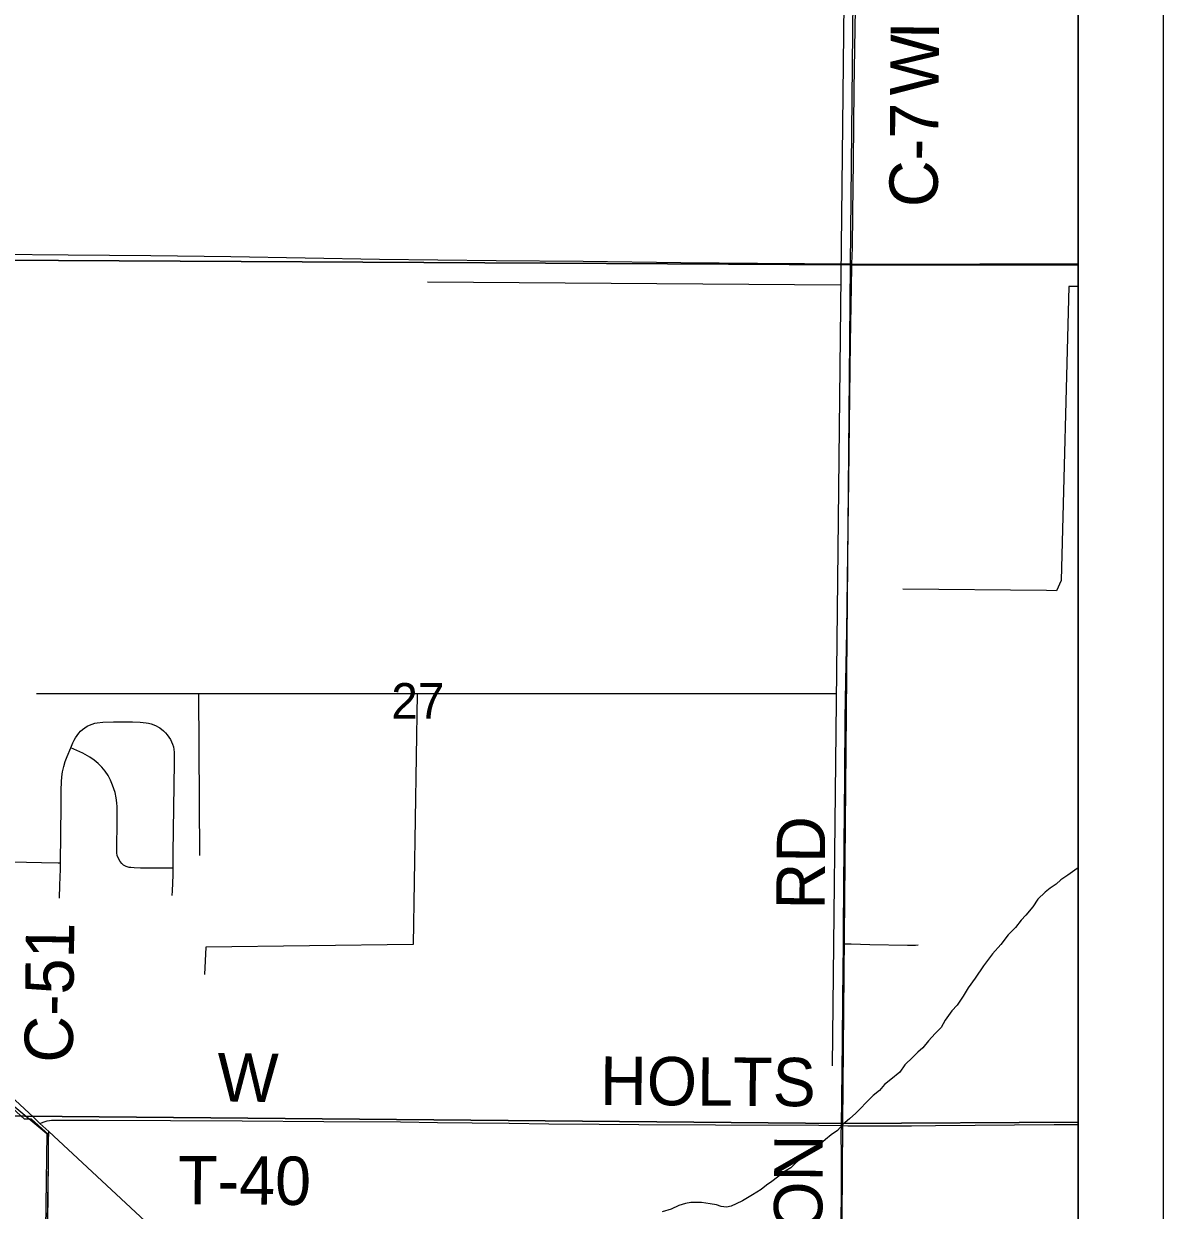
# Model space of a CAD drawing. Extents: x 0 to 34, y 0 to 22.
# Drawn here: x 7.662 to 9, y 15.265 to 16.658 of the extents above; entities that cross this region are included whole.
import ezdxf

# ---------------------------------------------------------------- set-up
doc = ezdxf.new("R2010")
doc.units = 0
for name, color, linetype in [('Default', 7, 'Continuous'), ('GM_X_City_Street', 7, 'Continuous'), ('GM_X_County_Road', 7, 'Continuous'), ('GM_X_County_Road_Text', 7, 'Continuous'), ('GM_X_Interstate_Route', 7, 'Continuous'), ('GM_X_Minor_River', 7, 'Continuous'), ('GM_X_Rail_Line', 7, 'Continuous'), ('GM_X_Section', 7, 'Continuous'), ('GM_X_Section_Text', 7, 'Continuous'), ('GM_X_State_Route', 7, 'Continuous'), ('GM_X_Township_Road', 7, 'Continuous'), ('GM_X_Township_Road_Text', 7, 'Continuous'), ('SH_Data', 7, 'Continuous')]:
    doc.layers.add(name, color=color, linetype=linetype)

msp = doc.modelspace()

# ---------------------------------------------------------------- linework, layer by layer
at = {"layer": 'Default'}
for points in [[(8.9, 16.3752), (8.9, 17.3884), (8.6426, 17.3907), (8.6324, 16.375)], [(8.9, 15.3679), (8.9, 16.3752), (8.6324, 16.375), (8.6234, 15.3665)], [(8.9, 14.3602), (8.9, 15.3679), (8.6234, 15.3665), (8.6163, 14.3591)]]:
    msp.add_lwpolyline(points, close=True, dxfattribs=at)
msp.add_lwpolyline([(7.6895, 15.2493), (7.6905, 15.323), (7.6906, 15.3451), (7.6906, 15.3534), (7.6708, 15.3714), (7.6625, 15.3715), (7.5256, 15.497)], dxfattribs=at)
at = {"layer": 'GM_X_City_Street'}
msp.add_lwpolyline([(7.6898, 15.2488), (7.6908, 15.3224), (7.6908, 15.3446), (7.6912, 15.3569)], dxfattribs=at)
at = {"layer": 'GM_X_County_Road'}
msp.add_lwpolyline([(8.6342, 16.3763), (8.6349, 16.395), (8.6355, 16.4353), (8.6362, 16.4974), (8.6371, 16.5811), (8.6381, 16.6525), (8.6401, 16.7673), (8.6405, 16.8107), (8.641, 16.851), (8.641, 16.879), (8.6415, 16.9251), (8.6423, 16.9966), (8.6427, 17.0214), (8.6428, 17.0275), (8.6432, 17.0337), (8.6436, 17.0377), (8.6447, 17.0437), (8.6458, 17.0492), (8.6475, 17.055), (8.6495, 17.0616), (8.666, 17.1117), (8.684, 17.1672), (8.6935, 17.1966), (8.696, 17.2047)], dxfattribs=at)
at = {"layer": 'GM_X_Interstate_Route'}
msp.add_lwpolyline([(8.9, 14.1), (8.9, 17.3895), (8.6473, 17.3907), (8.6467, 17.3907), (8.6346, 17.3907), (8.4804, 17.3959), (8.4711, 17.3964), (8.44, 17.397), (8.3187, 17.398), (8.2657, 17.3984), (8.1319, 17.3996), (8.079, 17.4004), (7.9794, 17.4011), (7.9078, 17.4018), (7.8424, 17.4022), (7.7241, 17.4025), (7.6681, 17.4026), (7.6399, 17.4028)], dxfattribs=at)
at = {"layer": 'GM_X_Minor_River'}
for points in [[(8.6229, 17.264), (8.6309, 17.2534), (8.611, 15.4343)], [(8.621, 16.351), (8.136, 16.3547)], [(8.9, 16.3497), (8.8891, 16.3497), (8.8799, 16.0041), (8.8746, 15.992), (8.8629, 15.9924), (8.6942, 15.994)], [(8.6158, 15.871), (7.6767, 15.8712)], [(7.867, 15.8712), (7.8681, 15.6813)], [(8.1237, 15.8711), (8.119, 15.5767), (7.8756, 15.5734), (7.8737, 15.5415)], [(8.9, 15.6665), (8.8988, 15.6658), (8.8881, 15.6582), (8.8798, 15.6525), (8.8741, 15.6476), (8.8673, 15.643), (8.8612, 15.6381), (8.8525, 15.6301), (8.8468, 15.621), (8.8385, 15.6111), (8.8332, 15.6051), (8.8263, 15.5967), (8.818, 15.588), (8.8093, 15.5766), (8.7994, 15.5656), (8.7888, 15.5516), (8.7789, 15.5371), (8.771, 15.5257), (8.7649, 15.5159), (8.7581, 15.5053), (8.7516, 15.4988), (8.744, 15.4878), (8.7391, 15.4791), (8.7319, 15.4722), (8.7243, 15.4635), (8.7175, 15.4552), (8.7118, 15.4502), (8.7057, 15.4442), (8.6966, 15.4354), (8.6906, 15.4267), (8.68, 15.4183), (8.6727, 15.4123), (8.6667, 15.4051), (8.6591, 15.3994), (8.6508, 15.3906), (8.6447, 15.3846), (8.639, 15.3785), (8.6314, 15.3721), (8.6235, 15.3652), (8.6174, 15.3584), (8.6098, 15.3531), (8.6034, 15.3478), (8.5973, 15.3425), (8.5889, 15.3353), (8.5825, 15.3311), (8.5761, 15.3265), (8.5689, 15.3208), (8.5624, 15.3144), (8.556, 15.3106), (8.5469, 15.3034), (8.5404, 15.2985), (8.534, 15.2939), (8.5279, 15.289), (8.5177, 15.2825), (8.5059, 15.2757), (8.4983, 15.2719), (8.4926, 15.2692), (8.487, 15.2681), (8.4809, 15.2689), (8.4752, 15.2708), (8.468, 15.2719), (8.4578, 15.2735), (8.4453, 15.2738), (8.4388, 15.2723), (8.4309, 15.2701), (8.4221, 15.2659), (8.4115, 15.2625)]]:
    msp.add_lwpolyline(points, dxfattribs=at)
at = {"layer": 'GM_X_Rail_Line'}
msp.add_lwpolyline([(7.6203, 15.4116), (7.6888, 15.3547), (7.6772, 14.5433), (7.683, 14.4528), (7.7895, 14.3507), (8.3611, 14.3552), (8.75, 14.3552), (8.9, 14.2113)], dxfattribs=at)
at = {"layer": 'GM_X_Section'}
for points in [[(7.639, 17.3962), (8.6426, 17.3907), (8.6324, 16.375), (7.6303, 16.3805)], [(7.6303, 16.3805), (8.6324, 16.375), (8.6234, 15.3665), (7.6191, 15.3755)], [(8.6234, 15.3665), (8.6163, 14.3591), (7.6069, 14.3511), (7.6191, 15.3755)]]:
    msp.add_lwpolyline(points, close=True, dxfattribs=at)
at = {"layer": 'GM_X_State_Route'}
for points in [[(7.9423, 15.1241), (7.9401, 15.126), (7.8926, 15.1691), (7.8474, 15.2116), (7.8268, 15.2306), (7.7928, 15.2623), (7.6912, 15.3569), (7.6806, 15.3666), (7.673, 15.3737), (7.6193, 15.4233)], [(7.6193, 15.4233), (7.673, 15.3737), (7.6806, 15.3666), (7.6912, 15.3569), (7.7928, 15.2623), (7.8268, 15.2306), (7.8474, 15.2116), (7.8926, 15.1691), (7.9401, 15.126), (7.9423, 15.1241)]]:
    msp.add_lwpolyline(points, dxfattribs=at)
at = {"layer": 'GM_X_Township_Road'}
for points in [[(7.6291, 16.3875), (7.7136, 16.387), (7.8109, 16.3859), (7.9047, 16.3847), (8.0794, 16.3818), (8.2166, 16.3802), (8.3186, 16.3793), (8.4335, 16.3779), (8.5236, 16.3771), (8.6342, 16.3763)], [(8.6243, 15.5775), (8.6243, 15.5965), (8.6248, 15.6431), (8.6251, 15.6929), (8.6258, 15.7737), (8.6264, 15.8421), (8.6271, 15.8856), (8.6283, 15.9447), (8.6286, 15.9758), (8.63, 16.0659), (8.6306, 16.1219), (8.6319, 16.2213), (8.6328, 16.2834), (8.6335, 16.3272), (8.6342, 16.3725), (8.6342, 16.3763)], [(8.6342, 16.3763), (8.6696, 16.376), (8.7846, 16.3764), (8.9, 16.3765)], [(7.7169, 15.8079), (7.7192, 15.8134), (7.7208, 15.8168), (7.7224, 15.8195), (7.7242, 15.8222), (7.7261, 15.8248), (7.7282, 15.8272), (7.7306, 15.8294), (7.7332, 15.8313), (7.7359, 15.8331), (7.7388, 15.8345), (7.7418, 15.8357), (7.7449, 15.8366), (7.748, 15.8372), (7.7544, 15.8379), (7.767, 15.8382), (7.7892, 15.8381), (7.7985, 15.8378), (7.802, 15.8376), (7.8053, 15.8371), (7.808, 15.8366), (7.8111, 15.8359), (7.8142, 15.8349), (7.8172, 15.8337), (7.82, 15.8321), (7.8216, 15.8311), (7.8259, 15.8276)], [(7.8259, 15.8276), (7.8282, 15.8254), (7.8302, 15.823), (7.8321, 15.8204), (7.8338, 15.8177), (7.8352, 15.8148), (7.8364, 15.8119), (7.8373, 15.8088), (7.8379, 15.8057), (7.8382, 15.8025), (7.8383, 15.79), (7.8368, 15.6843), (7.8368, 15.6663), (7.8368, 15.6583), (7.8361, 15.6398), (7.8356, 15.6344)], [(7.7048, 15.6726), (7.7054, 15.7394), (7.7057, 15.758), (7.7061, 15.7678), (7.7065, 15.7735), (7.7072, 15.7797), (7.7085, 15.7858), (7.7104, 15.7918), (7.7126, 15.7976), (7.7169, 15.8079)], [(7.8368, 15.6663), (7.8333, 15.6663), (7.8142, 15.6663), (7.7986, 15.6664), (7.7911, 15.6668), (7.7875, 15.667), (7.7853, 15.6672), (7.7831, 15.6678), (7.7817, 15.6683), (7.7788, 15.67), (7.7768, 15.6717), (7.7747, 15.6743), (7.7728, 15.6778), (7.7715, 15.6814), (7.771, 15.6845), (7.7708, 15.688), (7.7708, 15.6931), (7.7708, 15.6993), (7.7712, 15.711), (7.7715, 15.722), (7.7714, 15.7326), (7.7714, 15.7386), (7.771, 15.743), (7.7702, 15.7491), (7.7689, 15.7551), (7.7658, 15.7639), (7.7635, 15.7696), (7.7606, 15.7751), (7.7573, 15.7803), (7.7534, 15.7851), (7.7491, 15.7895), (7.7443, 15.7933), (7.7392, 15.7968), (7.7311, 15.8014), (7.7169, 15.8079)], [(7.6227, 15.6745), (7.629, 15.6743), (7.6826, 15.6729), (7.7022, 15.6726), (7.7048, 15.6726)], [(7.7035, 15.631), (7.7039, 15.6465), (7.7048, 15.665), (7.7048, 15.6726)], [(8.622, 15.3639), (8.6225, 15.3949), (8.6233, 15.463), (8.6236, 15.5127), (8.6243, 15.5775)], [(8.6243, 15.5775), (8.6334, 15.5773), (8.6554, 15.5768), (8.6995, 15.576), (8.7089, 15.5759), (8.712, 15.5762)], [(7.6806, 15.3666), (7.6857, 15.3684), (7.6891, 15.3695), (7.6918, 15.37), (7.6942, 15.3702), (7.6968, 15.3704), (7.7033, 15.3705), (7.7499, 15.3703), (7.9182, 15.3694), (8.0142, 15.3687), (8.1042, 15.3683), (8.1477, 15.3678), (8.1881, 15.3673), (8.2316, 15.3667), (8.2783, 15.3661), (8.3374, 15.3656), (8.384, 15.3654), (8.4741, 15.3647), (8.5954, 15.3645), (8.622, 15.3639)], [(8.6178, 14.4901), (8.6179, 14.5185), (8.618, 14.5651), (8.6181, 14.593), (8.6182, 14.6427), (8.6186, 14.7266), (8.6193, 14.7826), (8.6197, 14.8136), (8.6204, 14.882), (8.621, 14.9583), (8.6213, 15.0498), (8.6213, 15.121), (8.6217, 15.1647), (8.6216, 15.2082), (8.6219, 15.329), (8.6218, 15.3543), (8.622, 15.3639)], [(8.622, 15.3639), (8.6297, 15.3638), (8.7043, 15.3637), (8.7323, 15.364), (8.8719, 15.3652), (8.9, 15.3653)]]:
    msp.add_lwpolyline(points, dxfattribs=at)
at = {"layer": 'SH_Data'}
for p, q in [((9, 21), (9, 14)), ((8.9, 20.9), (8.9, 14.1))]:
    msp.add_line(p, q, dxfattribs=at)

# ---------------------------------------------------------------- texts
at = {"layer": 'GM_X_County_Road_Text'}
for s, height, rotation, p in [('W', 0.0568, 89.2723, (8.7358, 16.5735)), ('I', 0.0568, 89.2778, (8.7366, 16.6394)), ('C-7', 0.05682, 89.5419, (8.735, 16.4427)), ('C-51', 0.05682, 89.3151, (7.7191, 15.4376))]:
    msp.add_text(s, height=height, rotation=rotation, dxfattribs=at).set_placement(p)
at = {"layer": 'GM_X_Section_Text'}
msp.add_text('27', height=0.04186, rotation=0, dxfattribs=at).set_placement((8.0933, 15.8419))
at = {"layer": 'GM_X_Township_Road_Text'}
for s, height, rotation, p in [('RD', 0.05682, 89.5109, (8.6022, 15.6175)), ('W', 0.0568, 359.2868, (7.8888, 15.3925)), ('HOLTS', 0.05682, 359.5789, (8.3383, 15.3884)), ('MARTIN-WILLISTON', 0.056818, 89.6475, (8.5956, 14.6271)), ('T-40', 0.05682, 359.6469, (7.8427, 15.2716))]:
    msp.add_text(s, height=height, rotation=rotation, dxfattribs=at).set_placement(p)

doc.saveas('drawing.dxf')
